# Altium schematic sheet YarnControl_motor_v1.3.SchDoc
size A2
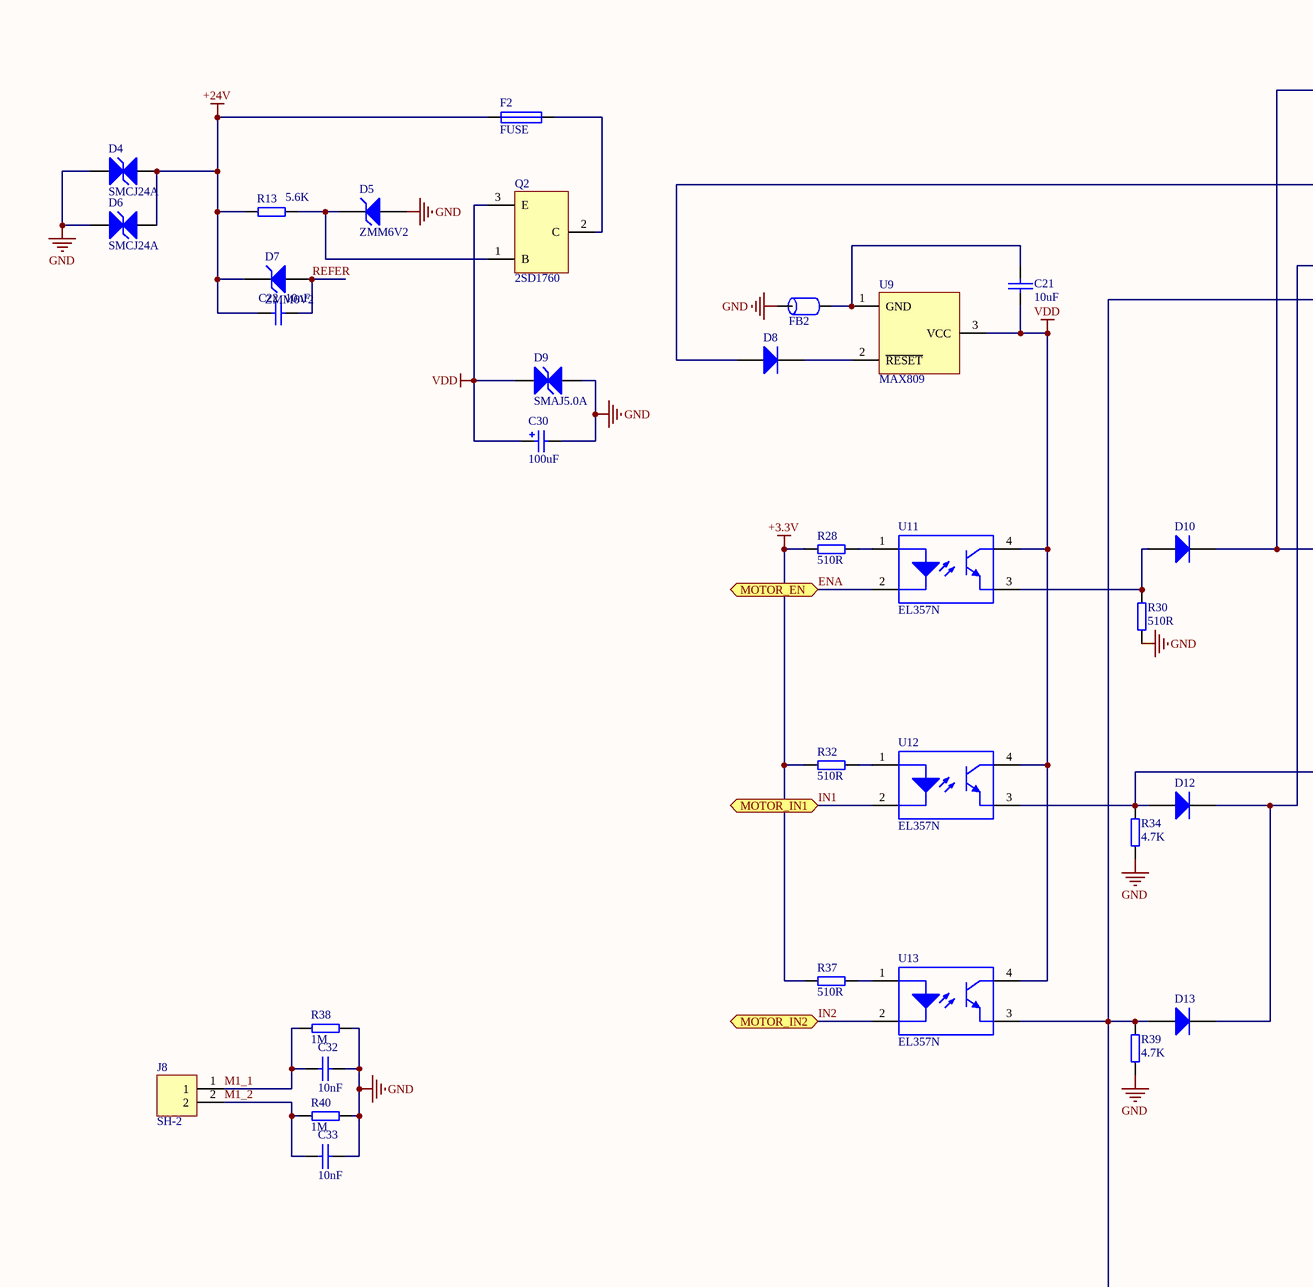
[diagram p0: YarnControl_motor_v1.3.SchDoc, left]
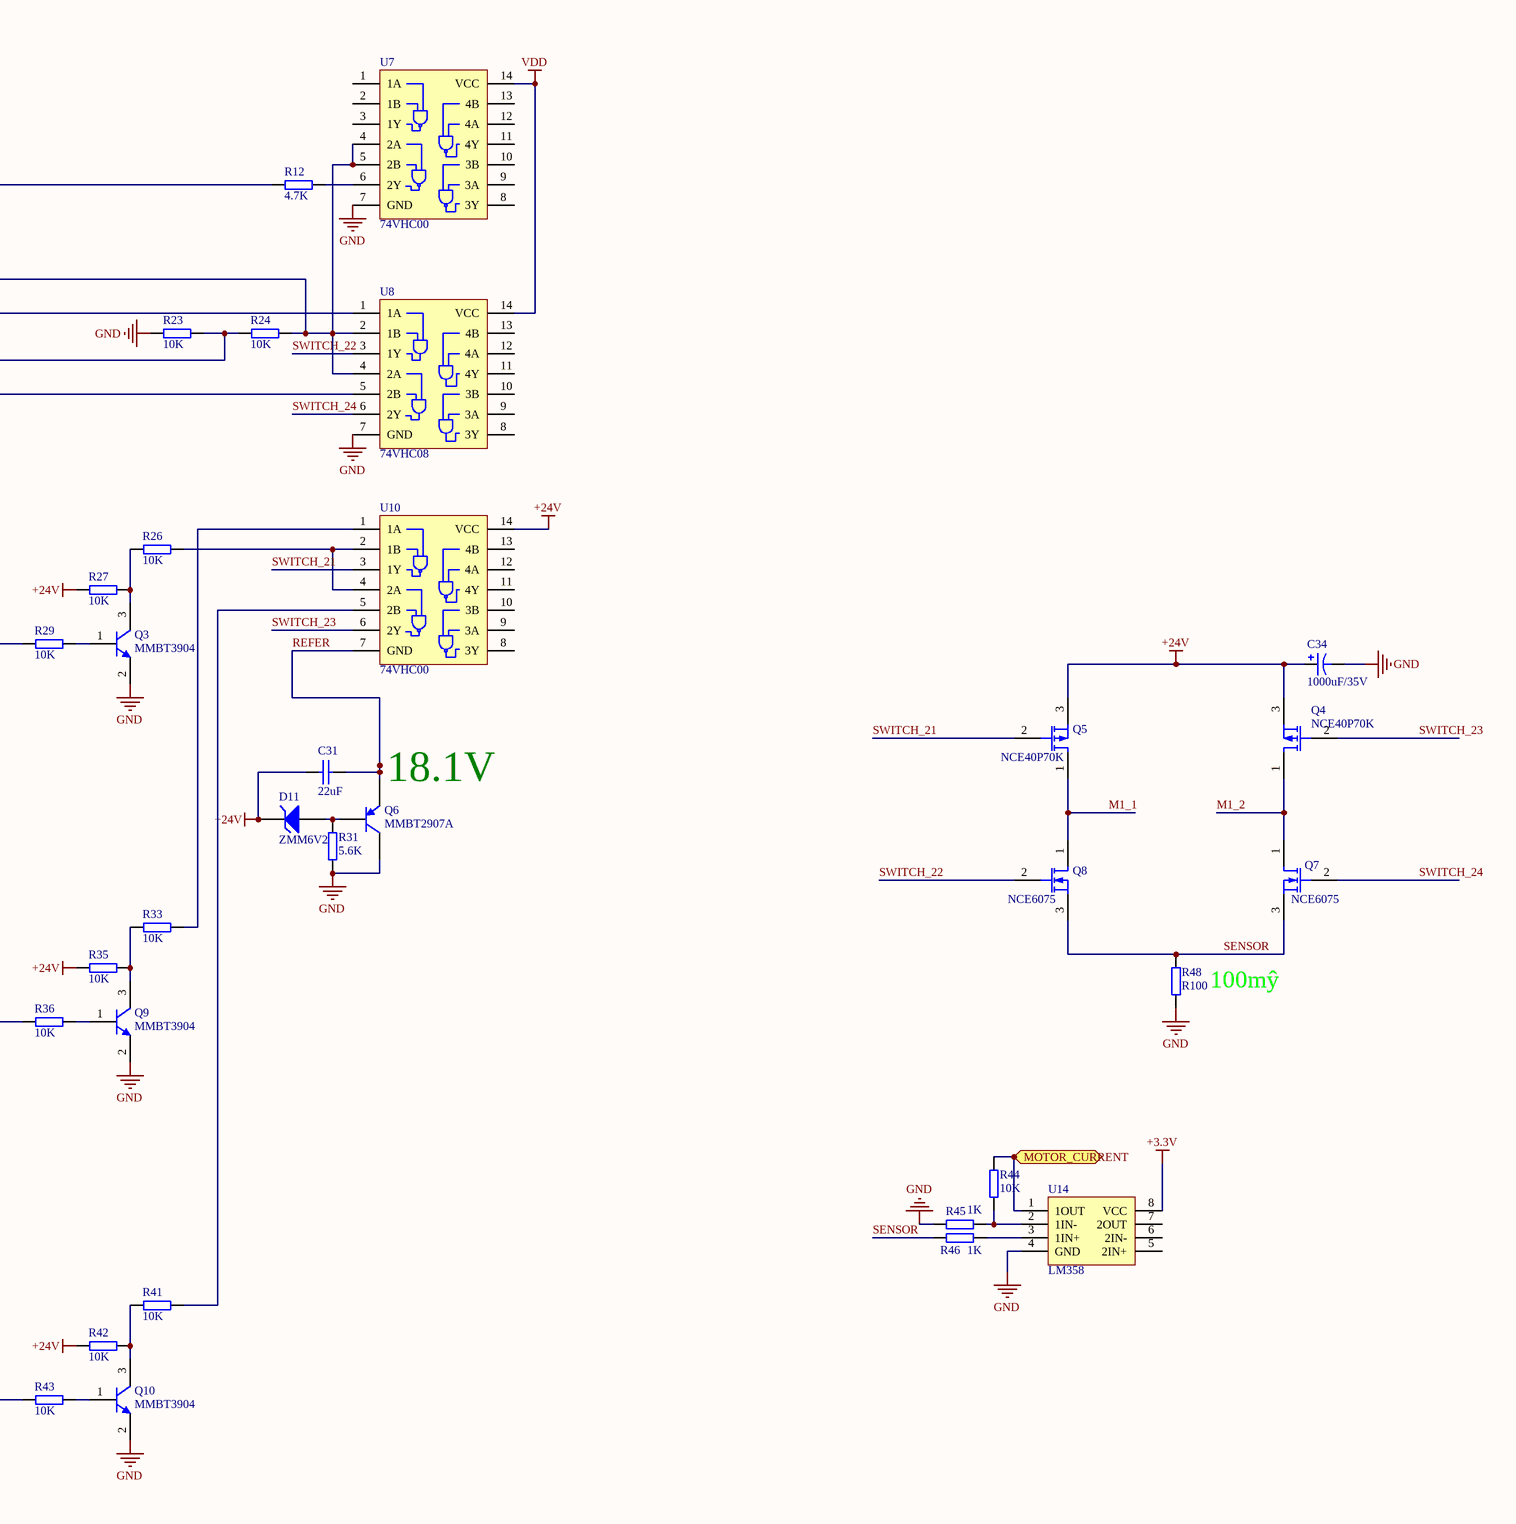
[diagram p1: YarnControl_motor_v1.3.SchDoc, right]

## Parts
C21  10uF  [0805]
C22  10nF  [0805]
C30  100uF  [CA6032-C]
C31  22uF  [0805]
C32  10nF  [0805]
C33  10nF  [0805]
C34  1000uF/35V  [CAP-5mm]
D4  SMCJ24A  [DO-214AA/SMB]
D5  ZMM6V2  [DIDODE_LL-34]
D6  SMCJ24A  [DO-214AA/SMB]
D7  ZMM6V2  [DIDODE_LL-34]
D8  1N4148  [DIDODE_LL-34]  (value not drawn)
D9  SMAJ5.0A  [Diode_TP2]
D10  1N4148  [DIDODE_LL-34]  (value not drawn)
D11  ZMM6V2  [DIDODE_LL-34]
D12  1N4148  [DIDODE_LL-34]  (value not drawn)
D13  1N4148  [DIDODE_LL-34]  (value not drawn)
F2  FUSE  [1206]
FB2  FERRITE  [0805]  (value not drawn)
J8  SH-2  [CH3.96-2P]
Q2  2SD1760  [TO-252-2L]
Q3  MMBT3904  [SOT-23]
Q4  NCE40P70K  [TO-252]
Q5  NCE40P70K  [TO-252]
Q6  MMBT2907A  [901X_SOT-23]
Q7  NCE6075  [TO-252]
Q8  NCE6075  [TO-252]
Q9  MMBT3904  [SOT-23]
Q10  MMBT3904  [SOT-23]
R12  4.7K  [0805]
R13  5.6K  [0805]
R23  10K  [0805]
R24  10K  [0805]
R26  10K  [0805]
R27  10K  [0805]
R28  510R  [0805]
R29  10K  [0805]
R30  510R  [0805]
R31  5.6K  [0805]
R32  510R  [0805]
R33  10K  [0805]
R34  4.7K  [0805]
R35  10K  [0805]
R36  10K  [0805]
R37  510R  [0805]
R38  1M  [0805]
R39  4.7K  [0805]
R40  1M  [0805]
R41  10K  [0805]
R42  10K  [0805]
R43  10K  [0805]
R44  10K  [0805]
R45  1K  [0805]
R46  1K  [0805]
R48  R100  [2512]
U7  74VHC00  [SO-14]
U8  74VHC08  [SO-14]
U9  MAX809  [SOT-23]
U10  74VHC00  [SO-14]
U11  EL357N  [EL357N]
U12  EL357N  [EL357N]
U13  EL357N  [EL357N]
U14  LM358  [SO-8]

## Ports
MOTOR_CURRENT, MOTOR_EN, MOTOR_IN1, MOTOR_IN2

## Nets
+3.3V: R28.1 R32.1 R37.1 U14.8(VCC)
+24V: C22.1 C31.2 C34.1 D4.1(A) D6.1(A) D7.2(K) D11.2(K) F2.2 Q4.3(S) Q5.3(S) R13.1 R27.1 R35.1 R42.1 U10.14(VCC)
GND: C30.2 C32.1 C33.1 C34.2 D4.2(K) D5.1(A) D6.2(K) D9.1(A) FB2.2 Q3.2(E) Q6.1(C) Q9.2(E) Q10.2(E) R23.1 R30.1 R31.1 R34.1 R38.2 R39.1 R40.2 R45.2 R48.1 U7.7(GND) U8.7(GND) U14.4(GND)
VDD: C21.1 C30.1 D9.2(K) Q2.3(E) U7.14(VCC) U8.14(VCC) U9.3(VCC) U11.4(C) U12.4(C) U13.4(C)
ENA: U11.2(Vin-) ; port MOTOR_EN
IN1: U12.2(Vin-) ; port MOTOR_IN1
IN2: U13.2(Vin-) ; port MOTOR_IN2
M1_1: C32.2 J8.1 Q5.1(D) Q8.1(D) R38.1
M1_2: C33.2 J8.2 Q4.1(D) Q7.1(D) R40.1
MOTOR_CURRENT: R44.1 U14.1(1OUT) ; port MOTOR_CURRENT
REFER: C22.2 C31.1 D7.1(A) Q6.3(E) U10.7(GND)
SENSOR: Q7.3(S) Q8.3(S) R46.2 R48.2
SWITCH_21: Q5.2(G) U10.3(1Y)
SWITCH_22: Q8.2(G) U8.3(1Y)
SWITCH_23: Q4.2(G) U10.6(2Y)
SWITCH_24: Q7.2(G) U8.6(2Y)
NetC21_2: C21.2 FB2.1 U9.1(GND)
NetD5_2: D5.2(K) Q2.1(B) R13.2
NetD8_1: D8.1(A) R24.2 U7.4(2A) U7.5(2B) U8.2(1B) U8.4(2A)
NetD8_2: D8.2(K) U9.2(~{RESET})
NetD10_1: D10.1(A) R30.2 U11.3(E)
NetD10_2: D10.2(K) R12.1 R29.1
NetD11_1: D11.1(A) Q6.2(B) R31.2
NetD12_1: D12.1(A) R34.2 R36.1 U8.1(1A) U12.3(E)
NetD12_2: D12.2(K) D13.2(K) R23.2 R24.1
NetD13_1: D13.1(A) R39.2 R43.1 U8.5(2B) U13.3(E)
NetF2_1: F2.1 Q2.2(C)
NetQ3_1: Q3.1(B) R29.2
NetQ3_3: Q3.3(C) R26.1 R27.2
NetQ9_1: Q9.1(B) R36.2
NetQ9_3: Q9.3(C) R33.1 R35.2
NetQ10_1: Q10.1(B) R43.2
NetQ10_3: Q10.3(C) R41.1 R42.2
NetR12_2: R12.2 U7.6(2Y)
NetR26_2: R26.2 U10.2(1B) U10.4(2A)
NetR28_2: R28.2 U11.1(Vin+)
NetR32_2: R32.2 U12.1(Vin+)
NetR33_2: R33.2 U10.1(1A)
NetR37_2: R37.2 U13.1(Vin+)
NetR41_2: R41.2 U10.5(2B)
NetR44_2: R44.2 R45.1 U14.2(1IN-)
NetR46_1: R46.1 U14.3(1IN+)

Not connected (* = marked no-connect by the designer): U7 1(1A) 2(1B) 3(1Y) 8(3Y) 9(3A) 10(3B) 11(4Y) 12(4A) 13(4B); U8 8(3Y) 9(3A) 10(3B) 11(4Y) 12(4A) 13(4B); U10 8(3Y) 9(3A) 10(3B) 11(4Y) 12(4A) 13(4B); U14 5(2IN+) 6(2IN-) 7(2OUT)

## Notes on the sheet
- (near Q6) 18.1V
- (near R48) 100mŷ

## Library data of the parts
C21 C22 C31-C33 = CAP: 电容
C30 = CapAEC*4
C34 = Cap Pol1: Polarized Capacitor (Radial)
D4 D6 D9 = TVS
D5 D7 D11 = D Zener: Zener Diode
D8 D10 D12 D13 = Diode: Default Diode
F2 = FUSE: 保险丝
Q3 Q9 Q10 = S8050
Q4 Q5 = MOSFET-P: P-Channel MOSFET
Q6 = PNP
Q7 Q8 = MOSFET-N: N-Channel MOSFET
R12 R13 R23 R24 R26-R46 R48 = RES: 电阻
U8 = 74HC08
U11-U13 = TLP521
